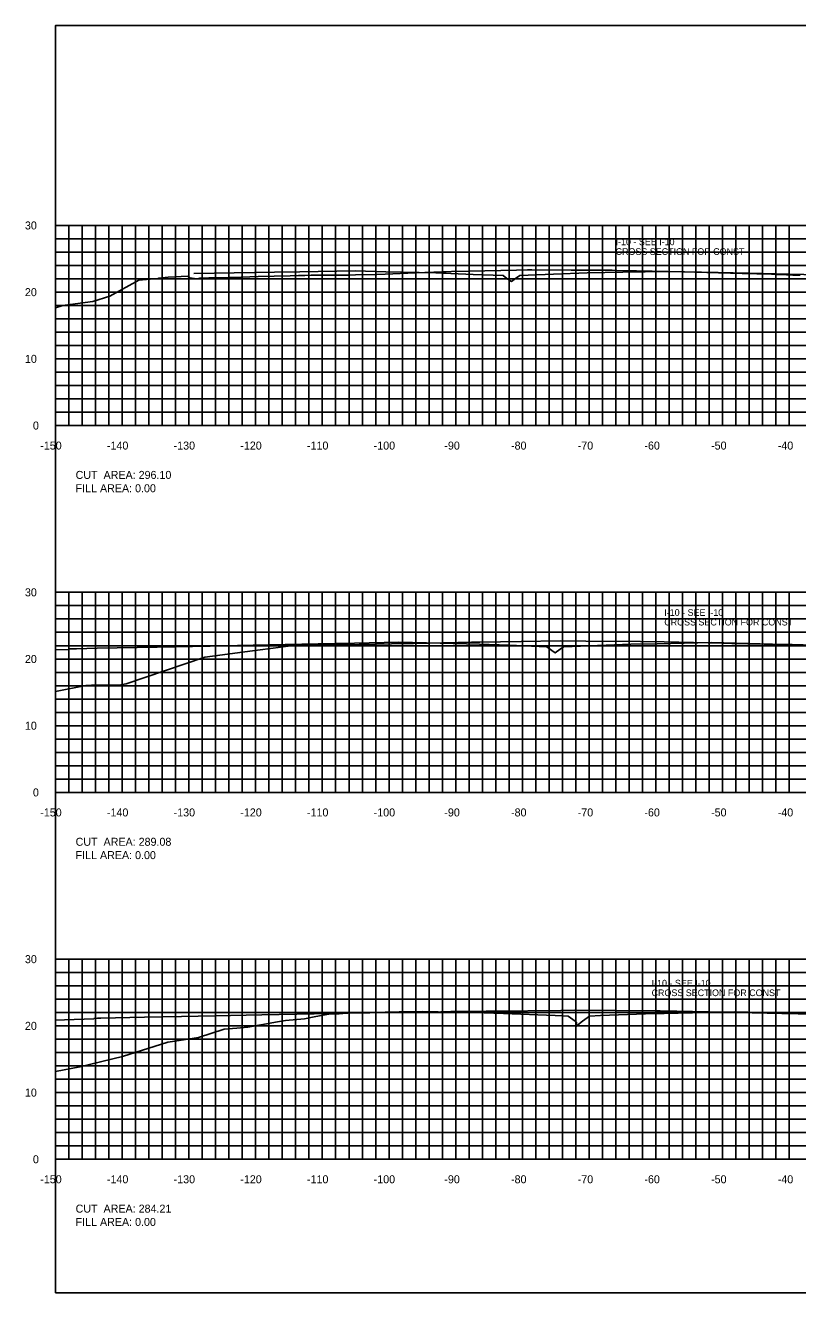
# Model space of a CAD drawing. Extents: x 1800976 to 1805104, y 250057 to 250580.
# Drawn here: x 1802136.5 to 1802252.3, y 250079.4 to 250269.4 of the extents above; entities that cross this region are included whole.
import ezdxf

# ---------------------------------------------------------------- set-up
doc = ezdxf.new("R2010")
doc.units = 0
for name, color, linetype in [('10', 7, 'Continuous'), ('3', 7, 'Continuous'), ('31', 7, 'Continuous'), ('60', 7, 'Continuous'), ('ANNO-TXT', 7, 'Continuous'), ('CL-CNST', 7, 'Continuous'), ('Level 62', 7, 'Continuous'), ('M-ROADS', 7, 'Continuous')]:
    doc.layers.add(name, color=color, linetype=linetype)

msp = doc.modelspace()

# ---------------------------------------------------------------- linework, layer by layer
msp.add_lwpolyline([(1802141, 250079.43), (1802441, 250079.43), (1802441, 250269.43), (1802141, 250269.43)], close=True)
at = {"layer": '60'}
for p, q in [((1802140.94, 250239.43), (1802141, 250239.43)), ((1802141, 250209.43), (1802141, 250239.43)), ((1802140.94, 250229.43), (1802141, 250229.43)), ((1802140.94, 250219.43), (1802141, 250219.43)), ((1802140.94, 250209.43), (1802141, 250209.43)), ((1802141, 250209.43), (1802441, 250209.43)), ((1802141, 250209.37), (1802141, 250209.43)), ((1802151, 250209.37), (1802151, 250209.43)), ((1802161, 250209.37), (1802161, 250209.43)), ((1802171, 250209.37), (1802171, 250209.43)), ((1802181, 250209.37), (1802181, 250209.43)), ((1802191, 250209.37), (1802191, 250209.43)), ((1802201, 250209.37), (1802201, 250209.43)), ((1802211, 250209.37), (1802211, 250209.43)), ((1802221, 250209.37), (1802221, 250209.43)), ((1802231, 250209.37), (1802231, 250209.43)), ((1802241, 250209.37), (1802241, 250209.43)), ((1802251, 250209.37), (1802251, 250209.43)), ((1802140.94, 250184.43), (1802141, 250184.43)), ((1802141, 250154.43), (1802141, 250184.43)), ((1802140.94, 250174.43), (1802141, 250174.43)), ((1802140.94, 250164.43), (1802141, 250164.43)), ((1802140.94, 250154.43), (1802141, 250154.43)), ((1802141, 250154.43), (1802441, 250154.43)), ((1802141, 250154.37), (1802141, 250154.43)), ((1802151, 250154.37), (1802151, 250154.43)), ((1802161, 250154.37), (1802161, 250154.43)), ((1802171, 250154.37), (1802171, 250154.43)), ((1802181, 250154.37), (1802181, 250154.43)), ((1802191, 250154.37), (1802191, 250154.43)), ((1802201, 250154.37), (1802201, 250154.43)), ((1802211, 250154.37), (1802211, 250154.43)), ((1802221, 250154.37), (1802221, 250154.43)), ((1802231, 250154.37), (1802231, 250154.43)), ((1802241, 250154.37), (1802241, 250154.43)), ((1802251, 250154.37), (1802251, 250154.43)), ((1802140.94, 250129.43), (1802141, 250129.43)), ((1802141, 250099.43), (1802141, 250129.43)), ((1802140.94, 250119.43), (1802141, 250119.43)), ((1802140.94, 250109.43), (1802141, 250109.43)), ((1802140.94, 250099.43), (1802141, 250099.43)), ((1802141, 250099.43), (1802441, 250099.43)), ((1802141, 250099.37), (1802141, 250099.43)), ((1802151, 250099.37), (1802151, 250099.43)), ((1802161, 250099.37), (1802161, 250099.43)), ((1802171, 250099.37), (1802171, 250099.43)), ((1802181, 250099.37), (1802181, 250099.43)), ((1802191, 250099.37), (1802191, 250099.43)), ((1802201, 250099.37), (1802201, 250099.43)), ((1802211, 250099.37), (1802211, 250099.43)), ((1802221, 250099.37), (1802221, 250099.43)), ((1802231, 250099.37), (1802231, 250099.43)), ((1802241, 250099.37), (1802241, 250099.43)), ((1802251, 250099.37), (1802251, 250099.43))]:
    msp.add_line(p, q, dxfattribs=at)
at = {"layer": 'CL-CNST'}
for points in [[(1802161.75, 250232.24), (1802164.79, 250232.3), (1802173.84, 250232.42), (1802177.65, 250232.49), (1802185.93, 250232.61), (1802190.51, 250232.5), (1802198.02, 250232.33), (1802203.63, 250232.1), (1802208.1, 250231.91), (1802208.69, 250231.48), (1802209.36, 250231.03), (1802209.96, 250231.47), (1802210.62, 250231.95), (1802215.69, 250232.14), (1802220.7, 250232.33), (1802226.08, 250232.41), (1802232.79, 250232.54), (1802240.34, 250232.36), (1802244.88, 250232.26), (1802253.2, 250232.06), (1802261, 250231.88)], [(1802141, 250175.79), (1802143.04, 250175.87), (1802143.05, 250175.88), (1802143.11, 250175.94), (1802143.87, 250175.97), (1802144.12, 250175.98), (1802147.25, 250176.04), (1802156.21, 250176.22), (1802164.16, 250176.38), (1802168.3, 250176.47), (1802172.97, 250176.56), (1802180.39, 250176.71), (1802185.83, 250176.82), (1802192.49, 250176.96), (1802198.69, 250176.82), (1802204.58, 250176.68), (1802208.97, 250176.5), (1802214.65, 250176.26), (1802215.4, 250175.71), (1802215.91, 250175.34), (1802216.67, 250175.89), (1802217.17, 250176.26), (1802223.58, 250176.5), (1802227.25, 250176.64), (1802231.2, 250176.72), (1802239.34, 250176.89), (1802248.52, 250176.68), (1802251.44, 250176.61), (1802261.38, 250176.32)], [(1802141, 250120.26), (1802142.33, 250120.31), (1802146.72, 250120.48), (1802146.75, 250120.52), (1802146.79, 250120.55), (1802147.28, 250120.57), (1802147.8, 250120.59), (1802154.32, 250120.72), (1802159.87, 250120.84), (1802164.86, 250120.94), (1802171.94, 250121.09), (1802179.8, 250121.25), (1802184.01, 250121.33), (1802192.54, 250121.51), (1802196.08, 250121.58), (1802205.28, 250121.37), (1802208.15, 250121.3), (1802215.94, 250120.98), (1802217.87, 250120.9), (1802218.9, 250120.15), (1802219.12, 250119.98), (1802219.12, 250119.38), (1802219.82, 250119.98), (1802220.04, 250120.14), (1802221.08, 250120.9), (1802222.71, 250120.96), (1802230.79, 250121.27), (1802232.24, 250121.3), (1802242.86, 250121.52), (1802254.65, 250121.25)]]:
    msp.add_lwpolyline(points, dxfattribs=at)
at = {"layer": 'Level 62'}
for p, q in [((1802141, 250239.43), (1802441, 250239.43)), ((1802141, 250209.43), (1802141, 250239.43)), ((1802143, 250209.43), (1802143, 250239.43)), ((1802145, 250209.43), (1802145, 250239.43)), ((1802147, 250209.43), (1802147, 250239.43)), ((1802149, 250209.43), (1802149, 250239.43)), ((1802151, 250209.43), (1802151, 250239.43)), ((1802153, 250209.43), (1802153, 250239.43)), ((1802155, 250209.43), (1802155, 250239.43)), ((1802157, 250209.43), (1802157, 250239.43)), ((1802159, 250209.43), (1802159, 250239.43)), ((1802161, 250209.43), (1802161, 250239.43)), ((1802163, 250209.43), (1802163, 250239.43)), ((1802165, 250209.43), (1802165, 250239.43)), ((1802167, 250209.43), (1802167, 250239.43)), ((1802169, 250209.43), (1802169, 250239.43)), ((1802171, 250209.43), (1802171, 250239.43)), ((1802173, 250209.43), (1802173, 250239.43)), ((1802175, 250209.43), (1802175, 250239.43)), ((1802177, 250209.43), (1802177, 250239.43)), ((1802179, 250209.43), (1802179, 250239.43)), ((1802181, 250209.43), (1802181, 250239.43)), ((1802183, 250209.43), (1802183, 250239.43)), ((1802185, 250209.43), (1802185, 250239.43)), ((1802187, 250209.43), (1802187, 250239.43)), ((1802189, 250209.43), (1802189, 250239.43)), ((1802191, 250209.43), (1802191, 250239.43)), ((1802193, 250209.43), (1802193, 250239.43)), ((1802195, 250209.43), (1802195, 250239.43)), ((1802197, 250209.43), (1802197, 250239.43)), ((1802199, 250209.43), (1802199, 250239.43)), ((1802201, 250209.43), (1802201, 250239.43)), ((1802203, 250209.43), (1802203, 250239.43)), ((1802205, 250209.43), (1802205, 250239.43)), ((1802207, 250209.43), (1802207, 250239.43)), ((1802209, 250209.43), (1802209, 250239.43)), ((1802211, 250209.43), (1802211, 250239.43)), ((1802213, 250209.43), (1802213, 250239.43)), ((1802215, 250209.43), (1802215, 250239.43)), ((1802217, 250209.43), (1802217, 250239.43)), ((1802219, 250209.43), (1802219, 250239.43)), ((1802221, 250209.43), (1802221, 250239.43)), ((1802223, 250209.43), (1802223, 250239.43)), ((1802225, 250209.43), (1802225, 250239.43)), ((1802227, 250209.43), (1802227, 250239.43)), ((1802229, 250209.43), (1802229, 250239.43)), ((1802231, 250209.43), (1802231, 250239.43)), ((1802233, 250209.43), (1802233, 250239.43)), ((1802235, 250209.43), (1802235, 250239.43)), ((1802237, 250209.43), (1802237, 250239.43)), ((1802239, 250209.43), (1802239, 250239.43)), ((1802241, 250209.43), (1802241, 250239.43)), ((1802243, 250209.43), (1802243, 250239.43)), ((1802245, 250209.43), (1802245, 250239.43)), ((1802247, 250209.43), (1802247, 250239.43)), ((1802249, 250209.43), (1802249, 250239.43)), ((1802251, 250209.43), (1802251, 250239.43)), ((1802141, 250237.43), (1802441, 250237.43)), ((1802141, 250235.43), (1802441, 250235.43)), ((1802141, 250233.43), (1802441, 250233.43)), ((1802141, 250231.43), (1802441, 250231.43)), ((1802141, 250229.43), (1802441, 250229.43)), ((1802141, 250227.43), (1802441, 250227.43)), ((1802141, 250225.43), (1802441, 250225.43)), ((1802141, 250223.43), (1802441, 250223.43)), ((1802141, 250221.43), (1802441, 250221.43)), ((1802141, 250219.43), (1802441, 250219.43)), ((1802141, 250217.43), (1802441, 250217.43)), ((1802141, 250215.43), (1802441, 250215.43)), ((1802141, 250213.43), (1802441, 250213.43)), ((1802141, 250211.43), (1802441, 250211.43)), ((1802141, 250209.43), (1802441, 250209.43)), ((1802141, 250184.43), (1802441, 250184.43)), ((1802141, 250154.43), (1802141, 250184.43)), ((1802143, 250154.43), (1802143, 250184.43)), ((1802145, 250154.43), (1802145, 250184.43)), ((1802147, 250154.43), (1802147, 250184.43)), ((1802149, 250154.43), (1802149, 250184.43)), ((1802151, 250154.43), (1802151, 250184.43)), ((1802153, 250154.43), (1802153, 250184.43)), ((1802155, 250154.43), (1802155, 250184.43)), ((1802157, 250154.43), (1802157, 250184.43)), ((1802159, 250154.43), (1802159, 250184.43)), ((1802161, 250154.43), (1802161, 250184.43)), ((1802163, 250154.43), (1802163, 250184.43)), ((1802165, 250154.43), (1802165, 250184.43)), ((1802167, 250154.43), (1802167, 250184.43)), ((1802169, 250154.43), (1802169, 250184.43)), ((1802171, 250154.43), (1802171, 250184.43)), ((1802173, 250154.43), (1802173, 250184.43)), ((1802175, 250154.43), (1802175, 250184.43)), ((1802177, 250154.43), (1802177, 250184.43)), ((1802179, 250154.43), (1802179, 250184.43)), ((1802181, 250154.43), (1802181, 250184.43)), ((1802183, 250154.43), (1802183, 250184.43)), ((1802185, 250154.43), (1802185, 250184.43)), ((1802187, 250154.43), (1802187, 250184.43)), ((1802189, 250154.43), (1802189, 250184.43)), ((1802191, 250154.43), (1802191, 250184.43)), ((1802193, 250154.43), (1802193, 250184.43)), ((1802195, 250154.43), (1802195, 250184.43)), ((1802197, 250154.43), (1802197, 250184.43)), ((1802199, 250154.43), (1802199, 250184.43)), ((1802201, 250154.43), (1802201, 250184.43)), ((1802203, 250154.43), (1802203, 250184.43)), ((1802205, 250154.43), (1802205, 250184.43)), ((1802207, 250154.43), (1802207, 250184.43)), ((1802209, 250154.43), (1802209, 250184.43)), ((1802211, 250154.43), (1802211, 250184.43)), ((1802213, 250154.43), (1802213, 250184.43)), ((1802215, 250154.43), (1802215, 250184.43)), ((1802217, 250154.43), (1802217, 250184.43)), ((1802219, 250154.43), (1802219, 250184.43)), ((1802221, 250154.43), (1802221, 250184.43)), ((1802223, 250154.43), (1802223, 250184.43)), ((1802225, 250154.43), (1802225, 250184.43)), ((1802227, 250154.43), (1802227, 250184.43)), ((1802229, 250154.43), (1802229, 250184.43)), ((1802231, 250154.43), (1802231, 250184.43)), ((1802233, 250154.43), (1802233, 250184.43)), ((1802235, 250154.43), (1802235, 250184.43)), ((1802237, 250154.43), (1802237, 250184.43)), ((1802239, 250154.43), (1802239, 250184.43)), ((1802241, 250154.43), (1802241, 250184.43)), ((1802243, 250154.43), (1802243, 250184.43)), ((1802245, 250154.43), (1802245, 250184.43)), ((1802247, 250154.43), (1802247, 250184.43)), ((1802249, 250154.43), (1802249, 250184.43)), ((1802251, 250154.43), (1802251, 250184.43)), ((1802141, 250182.43), (1802441, 250182.43)), ((1802141, 250180.43), (1802441, 250180.43)), ((1802141, 250178.43), (1802441, 250178.43)), ((1802141, 250176.43), (1802441, 250176.43)), ((1802141, 250174.43), (1802441, 250174.43)), ((1802141, 250172.43), (1802441, 250172.43)), ((1802141, 250170.43), (1802441, 250170.43)), ((1802141, 250168.43), (1802441, 250168.43)), ((1802141, 250166.43), (1802441, 250166.43)), ((1802141, 250164.43), (1802441, 250164.43)), ((1802141, 250162.43), (1802441, 250162.43)), ((1802141, 250160.43), (1802441, 250160.43)), ((1802141, 250158.43), (1802441, 250158.43)), ((1802141, 250156.43), (1802441, 250156.43)), ((1802141, 250154.43), (1802441, 250154.43)), ((1802141, 250129.43), (1802441, 250129.43)), ((1802141, 250099.43), (1802141, 250129.43)), ((1802143, 250099.43), (1802143, 250129.43)), ((1802145, 250099.43), (1802145, 250129.43)), ((1802147, 250099.43), (1802147, 250129.43)), ((1802149, 250099.43), (1802149, 250129.43)), ((1802151, 250099.43), (1802151, 250129.43)), ((1802153, 250099.43), (1802153, 250129.43)), ((1802155, 250099.43), (1802155, 250129.43)), ((1802157, 250099.43), (1802157, 250129.43)), ((1802159, 250099.43), (1802159, 250129.43)), ((1802161, 250099.43), (1802161, 250129.43)), ((1802163, 250099.43), (1802163, 250129.43)), ((1802165, 250099.43), (1802165, 250129.43)), ((1802167, 250099.43), (1802167, 250129.43)), ((1802169, 250099.43), (1802169, 250129.43)), ((1802171, 250099.43), (1802171, 250129.43)), ((1802173, 250099.43), (1802173, 250129.43)), ((1802175, 250099.43), (1802175, 250129.43)), ((1802177, 250099.43), (1802177, 250129.43)), ((1802179, 250099.43), (1802179, 250129.43)), ((1802181, 250099.43), (1802181, 250129.43)), ((1802183, 250099.43), (1802183, 250129.43)), ((1802185, 250099.43), (1802185, 250129.43)), ((1802187, 250099.43), (1802187, 250129.43)), ((1802189, 250099.43), (1802189, 250129.43)), ((1802191, 250099.43), (1802191, 250129.43)), ((1802193, 250099.43), (1802193, 250129.43)), ((1802195, 250099.43), (1802195, 250129.43)), ((1802197, 250099.43), (1802197, 250129.43)), ((1802199, 250099.43), (1802199, 250129.43)), ((1802201, 250099.43), (1802201, 250129.43)), ((1802203, 250099.43), (1802203, 250129.43)), ((1802205, 250099.43), (1802205, 250129.43)), ((1802207, 250099.43), (1802207, 250129.43)), ((1802209, 250099.43), (1802209, 250129.43)), ((1802211, 250099.43), (1802211, 250129.43)), ((1802213, 250099.43), (1802213, 250129.43)), ((1802215, 250099.43), (1802215, 250129.43)), ((1802217, 250099.43), (1802217, 250129.43)), ((1802219, 250099.43), (1802219, 250129.43)), ((1802221, 250099.43), (1802221, 250129.43)), ((1802223, 250099.43), (1802223, 250129.43)), ((1802225, 250099.43), (1802225, 250129.43)), ((1802227, 250099.43), (1802227, 250129.43)), ((1802229, 250099.43), (1802229, 250129.43)), ((1802231, 250099.43), (1802231, 250129.43)), ((1802233, 250099.43), (1802233, 250129.43)), ((1802235, 250099.43), (1802235, 250129.43)), ((1802237, 250099.43), (1802237, 250129.43)), ((1802239, 250099.43), (1802239, 250129.43)), ((1802241, 250099.43), (1802241, 250129.43)), ((1802243, 250099.43), (1802243, 250129.43)), ((1802245, 250099.43), (1802245, 250129.43)), ((1802247, 250099.43), (1802247, 250129.43)), ((1802249, 250099.43), (1802249, 250129.43)), ((1802251, 250099.43), (1802251, 250129.43)), ((1802141, 250127.43), (1802441, 250127.43)), ((1802141, 250125.43), (1802441, 250125.43)), ((1802141, 250123.43), (1802441, 250123.43)), ((1802141, 250121.43), (1802441, 250121.43)), ((1802141, 250119.43), (1802441, 250119.43)), ((1802141, 250117.43), (1802441, 250117.43)), ((1802141, 250115.43), (1802441, 250115.43)), ((1802141, 250113.43), (1802441, 250113.43)), ((1802141, 250111.43), (1802441, 250111.43)), ((1802141, 250109.43), (1802441, 250109.43)), ((1802141, 250107.43), (1802441, 250107.43)), ((1802141, 250105.43), (1802441, 250105.43)), ((1802141, 250103.43), (1802441, 250103.43)), ((1802141, 250101.43), (1802441, 250101.43)), ((1802141, 250099.43), (1802441, 250099.43))]:
    msp.add_line(p, q, dxfattribs=at)
at = {"layer": 'M-ROADS'}
for points in [[(1802141, 250227.07), (1802142.07, 250227.43), (1802143.93, 250227.67), (1802146.6, 250228.03), (1802149.14, 250228.83), (1802153.46, 250231.21), (1802155.77, 250231.42), (1802156.25, 250231.42), (1802156.46, 250231.51), (1802157.88, 250231.68), (1802160.85, 250231.84), (1802161.14, 250231.56), (1802162.17, 250231.45), (1802162.62, 250231.53), (1802163.61, 250231.53), (1802163.73, 250231.55), (1802163.98, 250231.57), (1802164.97, 250231.63), (1802165.42, 250231.59), (1802165.93, 250231.59), (1802166.3, 250231.56), (1802167.13, 250231.62), (1802167.59, 250231.65), (1802171.36, 250231.76), (1802176.17, 250231.88), (1802177.45, 250231.92), (1802178.39, 250231.95), (1802179.33, 250231.98), (1802179.68, 250231.99), (1802180.76, 250231.96), (1802180.96, 250231.96), (1802181.5, 250231.97), (1802182.25, 250232), (1802182.33, 250232), (1802183.53, 250231.96), (1802183.79, 250231.97), (1802184.81, 250231.99), (1802185.14, 250232), (1802185.95, 250232.02), (1802189.17, 250232.1), (1802190.42, 250232.13), (1802194.95, 250232.32), (1802199.14, 250232.48), (1802199.55, 250232.5), (1802200.39, 250232.54), (1802203.02, 250232.58), (1802210.1, 250232.73), (1802211.79, 250232.77), (1802212.42, 250232.78), (1802218.34, 250232.75), (1802224.46, 250232.71), (1802225.19, 250232.7), (1802228.12, 250232.64), (1802235.1, 250232.49), (1802236.85, 250232.45), (1802243.96, 250232.25), (1802248.36, 250232.13), (1802248.94, 250232.1), (1802249.61, 250232.07), (1802251.54, 250231.99), (1802252.64, 250231.96)], [(1802141, 250169.56), (1802145.52, 250170.44), (1802146.36, 250170.51), (1802148.35, 250170.51), (1802148.91, 250170.51), (1802150.54, 250170.51), (1802151.29, 250170.67), (1802151.57, 250170.73), (1802163.4, 250174.73), (1802171.29, 250175.77), (1802173.65, 250176.08), (1802176.65, 250176.46), (1802177.78, 250176.51), (1802177.93, 250176.52), (1802178.92, 250176.53), (1802179.63, 250176.54), (1802186.51, 250176.63), (1802191.35, 250176.73), (1802193.36, 250176.77), (1802193.71, 250176.77), (1802194.65, 250176.77), (1802201.34, 250176.9), (1802203.35, 250176.94), (1802204.32, 250176.96), (1802204.6, 250176.97), (1802210.84, 250177.06), (1802216.65, 250177.14), (1802220.5, 250177.12), (1802228.71, 250177.08), (1802232.26, 250177.01), (1802241.08, 250176.81), (1802241.47, 250176.8), (1802242.42, 250176.78), (1802249.64, 250176.61), (1802252.58, 250176.54)], [(1802141, 250112.58), (1802144.64, 250113.28), (1802151.05, 250114.86), (1802157.84, 250117), (1802159.53, 250117.25), (1802162.43, 250117.68), (1802166.26, 250118.93), (1802168.18, 250119.09), (1802169.81, 250119.22), (1802174.27, 250120.02), (1802175.49, 250120.21), (1802178.31, 250120.47), (1802180.03, 250120.83), (1802181.97, 250121.2), (1802183.35, 250121.23), (1802183.54, 250121.23), (1802184.62, 250121.31), (1802184.82, 250121.31), (1802191.46, 250121.41), (1802198.78, 250121.54), (1802199.56, 250121.55), (1802200.27, 250121.56), (1802201.3, 250121.59), (1802201.55, 250121.59), (1802202.87, 250121.6), (1802205.57, 250121.63), (1802206.06, 250121.63), (1802206.82, 250121.64), (1802216.76, 250121.74), (1802218.87, 250121.76), (1802225, 250121.73), (1802230.93, 250121.7), (1802231.66, 250121.69), (1802234.16, 250121.64), (1802241.21, 250121.49), (1802243.27, 250121.45), (1802249.89, 250121.29), (1802254.76, 250121.17)]]:
    msp.add_lwpolyline(points, dxfattribs=at)

# ---------------------------------------------------------------- texts
at = {"layer": '10'}
for s, p in [('-150', (1802138.7, 250205.83)), ('-140', (1802148.7, 250205.83)), ('-130', (1802158.7, 250205.83)), ('-120', (1802168.7, 250205.83)), ('-110', (1802178.7, 250205.83)), ('-100', (1802188.7, 250205.83)), ('-90', (1802199.3, 250205.83)), ('-80', (1802209.3, 250205.83)), ('-70', (1802219.3, 250205.83)), ('-60', (1802229.3, 250205.83)), ('-50', (1802239.3, 250205.83)), ('-40', (1802249.3, 250205.83)), ('-150', (1802138.7, 250150.83)), ('-140', (1802148.7, 250150.83)), ('-130', (1802158.7, 250150.83)), ('-120', (1802168.7, 250150.83)), ('-110', (1802178.7, 250150.83)), ('-100', (1802188.7, 250150.83)), ('-90', (1802199.3, 250150.83)), ('-80', (1802209.3, 250150.83)), ('-70', (1802219.3, 250150.83)), ('-60', (1802229.3, 250150.83)), ('-50', (1802239.3, 250150.83)), ('-40', (1802249.3, 250150.83)), ('-150', (1802138.7, 250095.83)), ('-140', (1802148.7, 250095.83)), ('-130', (1802158.7, 250095.83)), ('-120', (1802168.7, 250095.83)), ('-110', (1802178.7, 250095.83)), ('-100', (1802188.7, 250095.83)), ('-90', (1802199.3, 250095.83)), ('-80', (1802209.3, 250095.83)), ('-70', (1802219.3, 250095.83)), ('-60', (1802229.3, 250095.83)), ('-50', (1802239.3, 250095.83)), ('-40', (1802249.3, 250095.83))]:
    msp.add_text(s, height=1.2, dxfattribs=at).set_placement(p)
at = {"layer": '3'}
for s, p in [('CROSS SECTION FOR CONST ', (1802224.98, 250235.02)), ('I-10 - SEE I-10 ', (1802224.98, 250236.47)), ('I-10 - SEE I-10 ', (1802232.28, 250180.9)), ('CROSS SECTION FOR CONST ', (1802232.28, 250179.46)), ('I-10 - SEE I-10 ', (1802230.38, 250125.33)), ('CROSS SECTION FOR CONST ', (1802230.38, 250123.89))]:
    msp.add_text(s, height=1, dxfattribs=at).set_placement(p)
at = {"layer": '31'}
for s, p in [('30', (1802136.4, 250238.83)), ('20', (1802136.4, 250228.83)), ('10', (1802136.4, 250218.83)), ('0', (1802137.6, 250208.83)), ('30', (1802136.4, 250183.83)), ('20', (1802136.4, 250173.83)), ('10', (1802136.4, 250163.83)), ('0', (1802137.6, 250153.83)), ('30', (1802136.4, 250128.83)), ('20', (1802136.4, 250118.83)), ('10', (1802136.4, 250108.83)), ('0', (1802137.6, 250098.83))]:
    msp.add_text(s, height=1.2, dxfattribs=at).set_placement(p)
at = {"layer": '60'}
for p in [(1802141, 250209.43), (1802141, 250154.43), (1802141, 250099.43)]:
    msp.add_text('-', height=0.0001, dxfattribs=at).set_placement(p)
at = {"layer": 'ANNO-TXT'}
for s, p in [('CUT  AREA: 296.10', (1802144, 250201.43)), ('FILL AREA: 0.00', (1802144, 250199.43)), ('CUT  AREA: 289.08', (1802144, 250146.43)), ('FILL AREA: 0.00', (1802144, 250144.43)), ('CUT  AREA: 284.21', (1802144, 250091.43)), ('FILL AREA: 0.00', (1802144, 250089.43))]:
    msp.add_text(s, height=1.2, dxfattribs=at).set_placement(p)

doc.saveas('drawing.dxf')
